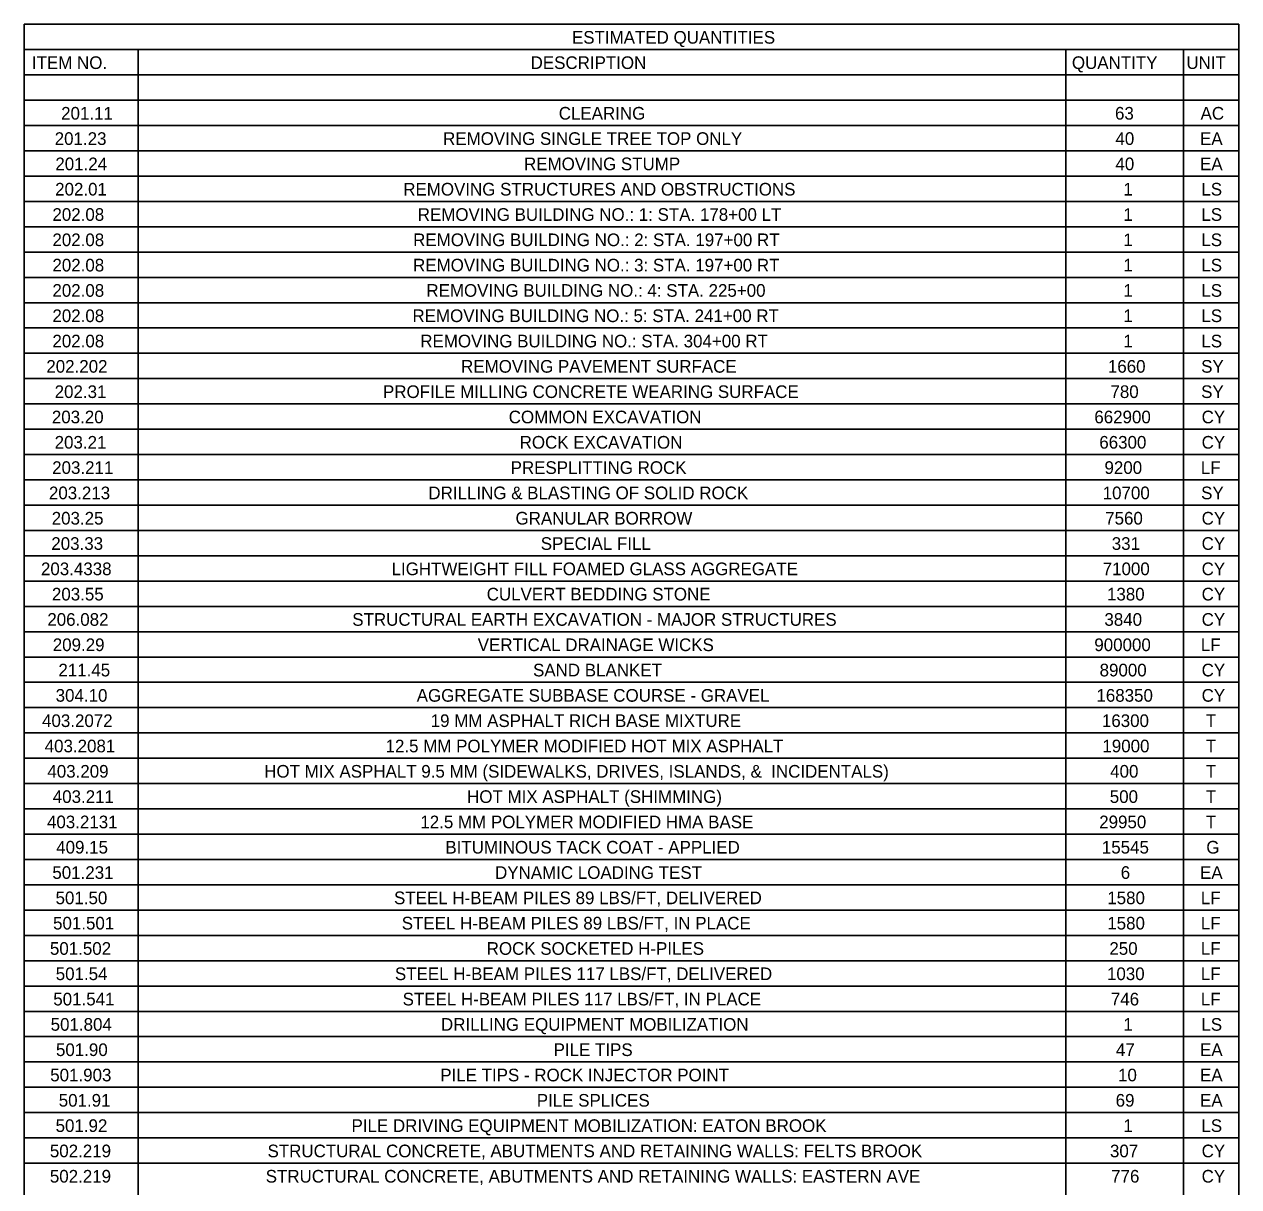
# Model space of a CAD drawing. Extents: x -18.7 to 5.6, y -2.7 to 5.1.
# Drawn here: x -18.69 to -17.746, y 3.071 to 3.975 of the extents above; entities that cross this region are included whole.
import ezdxf

# ---------------------------------------------------------------- set-up
doc = ezdxf.new("R2010")
doc.units = 0
doc.layers.add('ANNOTATION', color=7, linetype='Continuous')
doc.layers.add('BORDER', color=7, linetype='Continuous')

msp = doc.modelspace()

# ---------------------------------------------------------------- linework, layer by layer
at = {"layer": 'ANNOTATION'}
msp.add_line((-18.69032, 3.91573), (-18.60174, 3.91573), dxfattribs=at)
at = {"layer": 'BORDER'}
for p, q in [((-18.69032, 3.9551), (-17.74604, 3.9551)), ((-18.60174, 3.9551), (-18.60174, 2.24242)), ((-17.88042, 3.9551), (-17.88042, 2.24242)), ((-17.78903, 3.9551), (-17.78903, 2.24242)), ((-18.69032, 3.93542), (-17.74604, 3.93542)), ((-18.69032, 3.91573), (-17.74604, 3.91573)), ((-18.69032, 3.89604), (-17.74604, 3.89604)), ((-18.69032, 3.87636), (-17.74604, 3.87636)), ((-18.69032, 3.85667), (-17.74604, 3.85667)), ((-18.69032, 3.83699), (-17.74604, 3.83699)), ((-18.69032, 3.8173), (-17.74604, 3.8173)), ((-18.69032, 3.79761), (-17.74604, 3.79761)), ((-18.69032, 3.77793), (-17.74604, 3.77793)), ((-18.69032, 3.75824), (-17.74604, 3.75824)), ((-18.69032, 3.73856), (-17.74604, 3.73856)), ((-18.69032, 3.71887), (-17.74604, 3.71887)), ((-18.69032, 3.69918), (-17.74604, 3.69918)), ((-18.69032, 3.6795), (-17.74604, 3.6795)), ((-18.69032, 3.65981), (-17.74604, 3.65981)), ((-18.69032, 3.64013), (-17.74604, 3.64013)), ((-18.69032, 3.62044), (-17.74604, 3.62044)), ((-18.69032, 3.60075), (-17.74604, 3.60075)), ((-18.69032, 3.58107), (-17.74604, 3.58107)), ((-18.69032, 3.56138), (-17.74604, 3.56138)), ((-18.69032, 3.5417), (-17.74604, 3.5417)), ((-18.69032, 3.52201), (-17.74604, 3.52201)), ((-18.69032, 3.50232), (-17.74604, 3.50232)), ((-18.69032, 3.48264), (-17.74604, 3.48264)), ((-18.69032, 3.46295), (-17.74604, 3.46295)), ((-18.69032, 3.44327), (-17.74604, 3.44327)), ((-18.69032, 3.42358), (-17.74604, 3.42358)), ((-18.69032, 3.40389), (-17.74604, 3.40389)), ((-18.69032, 3.38421), (-17.74604, 3.38421)), ((-18.69032, 3.36452), (-17.74604, 3.36452)), ((-18.69032, 3.34484), (-17.74604, 3.34484)), ((-18.69032, 3.32515), (-17.74604, 3.32515)), ((-18.69032, 3.30546), (-17.74604, 3.30546)), ((-18.69032, 3.28578), (-17.74604, 3.28578)), ((-18.69032, 3.26609), (-17.74604, 3.26609)), ((-18.69032, 3.24641), (-17.74604, 3.24641)), ((-18.69032, 3.22672), (-17.74604, 3.22672)), ((-18.69032, 3.20703), (-17.74604, 3.20703)), ((-18.69032, 3.18735), (-17.74604, 3.18735)), ((-18.69032, 3.16766), (-17.74604, 3.16766)), ((-18.69032, 3.14798), (-17.74604, 3.14798)), ((-18.69032, 3.12829), (-17.74604, 3.12829)), ((-18.69032, 3.1086), (-17.74604, 3.1086)), ((-18.69032, 3.08892), (-17.74604, 3.08892))]:
    msp.add_line(p, q, dxfattribs=at)
msp.add_lwpolyline([(-18.69032, 3.97479), (-17.74604, 3.97479), (-17.74604, 2.24242), (-18.69032, 2.24242)], close=True, dxfattribs=at)

# ---------------------------------------------------------------- texts
at = {"layer": 'ANNOTATION'}
for s, height, p in [('201.11', 0.009843, (-18.66167, 3.90064)), ('CLEARING', 0.009843, (-18.27474, 3.90064)), ('63', 0.009843, (-17.84223, 3.90064)), ('AC', 0.009843, (-17.77569, 3.90064)), ('201.23', 0.009843, (-18.66667, 3.88095)), ('REMOVING SINGLE TREE TOP ONLY', 0.009843, (-18.36468, 3.88095)), ('40', 0.009843, (-17.84189, 3.88095)), ('EA', 0.009843, (-17.77611, 3.88095)), ('201.24', 0.009843, (-18.66617, 3.86127)), ('REMOVING STUMP', 0.009843, (-18.30174, 3.86127)), ('40', 0.009843, (-17.84189, 3.86127)), ('EA', 0.009843, (-17.77611, 3.86127)), ('202.01', 0.009843, (-18.66632, 3.84158)), ('REMOVING STRUCTURES AND OBSTRUCTIONS', 0.009843, (-18.39566, 3.84158)), ('1', 0.00984, (-17.83576, 3.84158)), ('LS', 0.009843, (-17.77506, 3.84158)), ('202.08', 0.009843, (-18.66845, 3.8219)), ('REMOVING BUILDING NO.: 1: STA. 178+00 LT', 0.009843, (-18.38439, 3.8219)), ('1', 0.00984, (-17.83576, 3.8219)), ('LS', 0.009843, (-17.77506, 3.8219)), ('202.08', 0.009843, (-18.66845, 3.80221)), ('REMOVING BUILDING NO.: 2: STA. 197+00 RT', 0.009843, (-18.38795, 3.80221)), ('1', 0.00984, (-17.83576, 3.80221)), ('LS', 0.009843, (-17.77506, 3.80221)), ('202.08', 0.009843, (-18.66845, 3.78252)), ('REMOVING BUILDING NO.: 3: STA. 197+00 RT', 0.009843, (-18.38803, 3.78252)), ('1', 0.00984, (-17.83576, 3.78252)), ('LS', 0.009843, (-17.77506, 3.78252)), ('202.08', 0.009843, (-18.66845, 3.76284)), ('REMOVING BUILDING NO.: 4: STA. 225+00', 0.009843, (-18.37765, 3.76284)), ('1', 0.00984, (-17.83576, 3.76284)), ('LS', 0.009843, (-17.77506, 3.76284)), ('202.08', 0.009843, (-18.66845, 3.74315)), ('REMOVING BUILDING NO.: 5: STA. 241+00 RT', 0.009843, (-18.38849, 3.74315)), ('1', 0.00984, (-17.83576, 3.74315)), ('LS', 0.009843, (-17.77506, 3.74315)), ('202.08', 0.009843, (-18.66845, 3.72347)), ('REMOVING BUILDING NO.: STA. 304+00 RT', 0.009843, (-18.3824, 3.72347)), ('1', 0.00984, (-17.83576, 3.72347)), ('LS', 0.009843, (-17.77506, 3.72347)), ('202.202', 0.009843, (-18.67318, 3.70378)), ('REMOVING PAVEMENT SURFACE', 0.009843, (-18.35068, 3.70378)), ('1660', 0.009843, (-17.84777, 3.70378)), ('SY', 0.009843, (-17.77526, 3.70378)), ('202.31', 0.009843, (-18.66671, 3.68409)), ('PROFILE MILLING CONCRETE WEARING SURFACE', 0.009843, (-18.41139, 3.68409)), ('780', 0.009843, (-17.84576, 3.68409)), ('SY', 0.009843, (-17.77526, 3.68409)), ('203.20', 0.009843, (-18.66888, 3.66441)), ('COMMON EXCAVATION', 0.009843, (-18.31364, 3.66441)), ('662900', 0.009843, (-17.85831, 3.66441)), ('CY', 0.009843, (-17.77487, 3.66441)), ('203.21', 0.009843, (-18.66671, 3.64472)), ('ROCK EXCAVATION', 0.009843, (-18.30514, 3.64472)), ('66300', 0.009843, (-17.85444, 3.64472)), ('CY', 0.009843, (-17.77487, 3.64472)), ('203.211', 0.009843, (-18.66865, 3.62504)), ('PRESPLITTING ROCK', 0.009843, (-18.31215, 3.62504)), ('9200', 0.009843, (-17.85041, 3.62504)), ('LF', 0.009843, (-17.77549, 3.62504)), ('203.213', 0.009843, (-18.67116, 3.60535)), ('DRILLING & BLASTING OF SOLID ROCK       ', 0.009843, (-18.3761, 3.60535)), ('10700', 0.009843, (-17.8518, 3.60535)), ('SY', 0.009843, (-17.77526, 3.60535)), ('203.25', 0.009843, (-18.669, 3.58566)), ('GRANULAR BORROW', 0.009843, (-18.30836, 3.58566)), ('7560', 0.009843, (-17.84987, 3.58566)), ('CY', 0.009843, (-17.77487, 3.58566)), ('203.33', 0.009843, (-18.66931, 3.56598)), ('SPECIAL FILL', 0.009843, (-18.28874, 3.56598)), ('331', 0.009843, (-17.84475, 3.56598)), ('CY', 0.009843, (-17.77487, 3.56598)), ('203.4338', 0.009843, (-18.67736, 3.54629)), ('LIGHTWEIGHT FILL FOAMED GLASS AGGREGATE', 0.009843, (-18.40474, 3.54629)), ('71000', 0.009843, (-17.8518, 3.54629)), ('CY', 0.009843, (-17.77487, 3.54629)), ('203.55', 0.009843, (-18.66884, 3.52661)), ('CULVERT BEDDING STONE', 0.009843, (-18.33077, 3.52661)), ('1380', 0.009843, (-17.84847, 3.52661)), ('CY', 0.009843, (-17.77487, 3.52661)), ('206.082', 0.009843, (-18.67241, 3.50692)), ('STRUCTURAL EARTH EXCAVATION - MAJOR STRUCTURES', 0.009843, (-18.43529, 3.50692)), ('3840', 0.009843, (-17.85048, 3.50692)), ('CY', 0.009843, (-17.77487, 3.50692)), ('209.29', 0.009843, (-18.66818, 3.48723)), ('VERTICAL DRAINAGE WICKS', 0.009843, (-18.33772, 3.48723)), ('900000', 0.009843, (-17.85831, 3.48723)), ('LF', 0.009843, (-17.77549, 3.48723)), ('211.45', 0.009843, (-18.6638, 3.46755)), ('SAND BLANKET', 0.009843, (-18.29473, 3.46755)), ('89000', 0.009843, (-17.8542, 3.46755)), ('CY', 0.009843, (-17.77487, 3.46755)), ('304.10', 0.009843, (-18.66593, 3.44786)), ('AGGREGATE SUBBASE COURSE - GRAVEL', 0.009843, (-18.38521, 3.44786)), ('168350', 0.009843, (-17.85668, 3.44786)), ('CY', 0.009843, (-17.77487, 3.44786)), ('403.2072', 0.009843, (-18.67651, 3.42818)), ('19 MM ASPHALT RICH BASE MIXTURE', 0.009843, (-18.37432, 3.42818)), ('16300', 0.009843, (-17.85242, 3.42818)), ('T', 0.00984, (-17.77162, 3.42818)), ('403.2081', 0.009843, (-18.67446, 3.40849)), ('12.5 MM POLYMER MODIFIED HOT MIX ASPHALT', 0.009843, (-18.4094, 3.40849)), ('19000', 0.009843, (-17.85203, 3.40849)), ('T', 0.00984, (-17.77162, 3.40849)), ('403.209', 0.009843, (-18.67237, 3.3888)), ('HOT MIX ASPHALT 9.5 MM (SIDEWALKS, DRIVES, ISLANDS, &  INCIDENTALS)', 0.009843, (-18.50376, 3.3888)), ('400', 0.009843, (-17.84599, 3.3888)), ('T', 0.00984, (-17.77162, 3.3888)), ('403.211', 0.009843, (-18.66818, 3.36912)), ('HOT MIX ASPHALT (SHIMMING)', 0.009843, (-18.34602, 3.36912)), ('500', 0.009843, (-17.8463, 3.36912)), ('T', 0.00984, (-17.77162, 3.36912)), ('403.2131', 0.009843, (-18.67267, 3.34943)), ('12.5 MM POLYMER MODIFIED HMA BASE', 0.009843, (-18.38236, 3.34943)), ('29950', 0.009843, (-17.85451, 3.34943)), ('T', 0.00984, (-17.77162, 3.34943)), ('409.15', 0.009843, (-18.66551, 3.32975)), ('BITUMINOUS TACK COAT - APPLIED', 0.009843, (-18.36289, 3.32975)), ('15545', 0.009843, (-17.85246, 3.32975)), ('G', 0.00984, (-17.77123, 3.32975)), ('501.231', 0.009843, (-18.66849, 3.31006)), ('DYNAMIC LOADING TEST', 0.009843, (-18.32425, 3.31006)), ('6', 0.00984, (-17.83778, 3.31006)), ('EA', 0.009843, (-17.77611, 3.31006)), ('501.50', 0.009843, (-18.66601, 3.29037)), ('STEEL H-BEAM PILES 89 LBS/FT, DELIVERED', 0.009843, (-18.40283, 3.29037)), ('1580', 0.009843, (-17.84824, 3.29037)), ('LF', 0.009843, (-17.77549, 3.29037)), ('501.501', 0.009843, (-18.66795, 3.27069)), ('STEEL H-BEAM PILES 89 LBS/FT, IN PLACE', 0.009843, (-18.39684, 3.27069)), ('1580', 0.009843, (-17.84824, 3.27069)), ('LF', 0.009843, (-17.77549, 3.27069)), ('501.502', 0.009843, (-18.67039, 3.251)), ('ROCK SOCKETED H-PILES', 0.009843, (-18.33076, 3.251)), ('250', 0.009843, (-17.84661, 3.251)), ('LF', 0.009843, (-17.77549, 3.251)), ('501.54', 0.009843, (-18.66586, 3.23132)), ('STEEL H-BEAM PILES 117 LBS/FT, DELIVERED', 0.009843, (-18.40213, 3.23132)), ('1030', 0.009843, (-17.84847, 3.23132)), ('LF', 0.009843, (-17.77549, 3.23132)), ('501.541', 0.009843, (-18.66779, 3.21163)), ('STEEL H-BEAM PILES 117 LBS/FT, IN PLACE', 0.009843, (-18.39614, 3.21163)), ('746', 0.009843, (-17.84545, 3.21163)), ('LF', 0.009843, (-17.77549, 3.21163)), ('501.804', 0.009843, (-18.66981, 3.19194)), ('DRILLING EQUIPMENT MOBILIZATION', 0.009843, (-18.3663, 3.19194)), ('1', 0.00984, (-17.83576, 3.19194)), ('LS', 0.009843, (-17.77506, 3.19194)), ('501.90', 0.009843, (-18.6657, 3.17226)), ('PILE TIPS', 0.009843, (-18.27873, 3.17226)), ('47', 0.009843, (-17.8415, 3.17226)), ('EA', 0.009843, (-17.77611, 3.17226)), ('501.903', 0.009843, (-18.67016, 3.15257)), ('PILE TIPS - ROCK INJECTOR POINT', 0.009843, (-18.36689, 3.15257)), ('10', 0.009843, (-17.83987, 3.15257)), ('EA', 0.009843, (-17.77611, 3.15257)), ('501.91', 0.009843, (-18.66353, 3.13289)), ('PILE SPLICES', 0.009843, (-18.29183, 3.13289)), ('69', 0.009843, (-17.84173, 3.13289)), ('EA', 0.009843, (-17.77611, 3.13289)), ('501.92', 0.009843, (-18.66597, 3.1132)), ('PILE DRIVING EQUIPMENT MOBILIZATION: EATON BROOK', 0.009843, (-18.43588, 3.1132)), ('1', 0.00984, (-17.83576, 3.1132)), ('LS', 0.009843, (-17.77506, 3.1132)), ('502.219', 0.009843, (-18.67043, 3.09351)), ('STRUCTURAL CONCRETE, ABUTMENTS AND RETAINING WALLS: FELTS BROOK', 0.009843, (-18.50118, 3.09351)), ('307', 0.009843, (-17.84615, 3.09351)), ('CY', 0.009843, (-17.77487, 3.09351)), ('502.219', 0.009843, (-18.67043, 3.07383)), ('STRUCTURAL CONCRETE, ABUTMENTS AND RETAINING WALLS: EASTERN AVE', 0.009843, (-18.50259, 3.07383)), ('776', 0.009843, (-17.84522, 3.07383)), ('CY', 0.009843, (-17.77487, 3.07383))]:
    msp.add_text(s, height=height, dxfattribs=at).set_placement(p)
at = {"layer": 'BORDER'}
for s, height, p in [('ESTIMATED QUANTITIES', 0.0098425, (-18.26447, 3.9597)), ('ITEM NO.', 0.009843, (-18.68441, 3.94001)), ('DESCRIPTION', 0.0098425, (-18.29662, 3.94001)), ('QUANTITY', 0.009843, (-17.87574, 3.94001)), ('UNIT', 0.009843, (-17.78672, 3.94001))]:
    msp.add_text(s, height=height, dxfattribs=at).set_placement(p)

doc.saveas('drawing.dxf')
